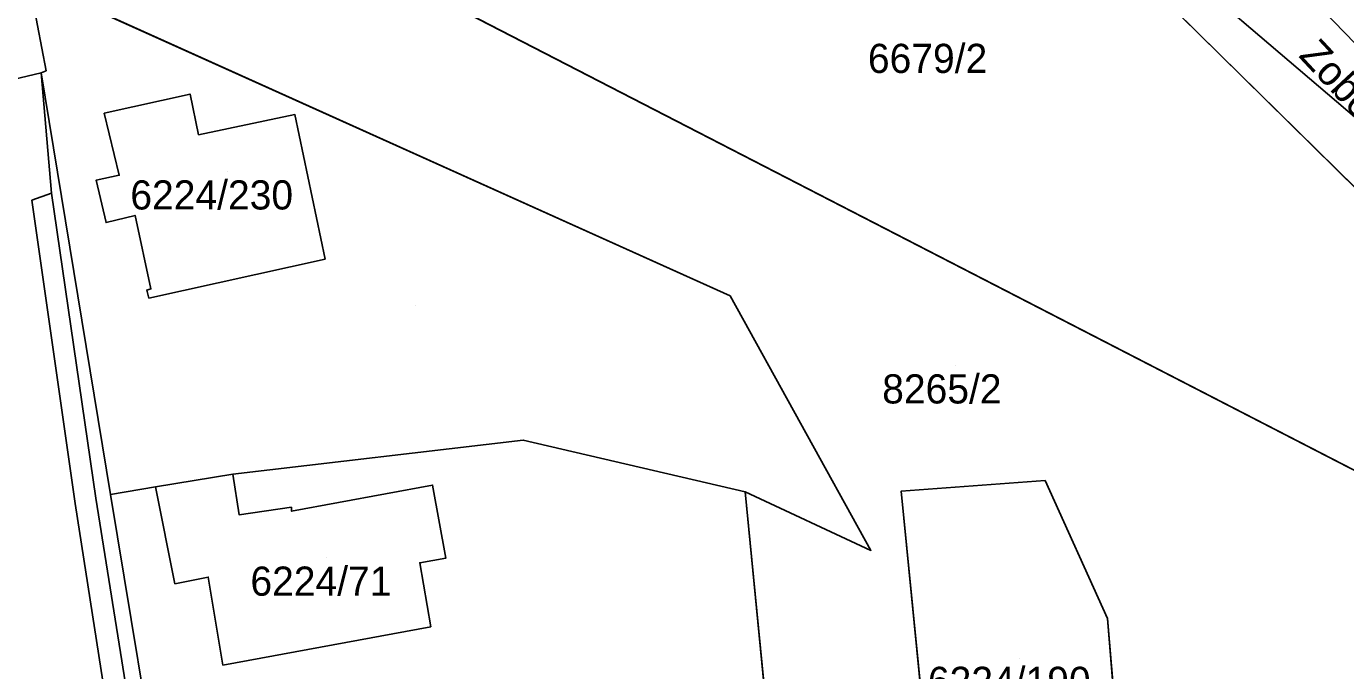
# Model space of a CAD drawing. Extents: x -266199 to -261993, y -1239047 to -1235108.
# Drawn here: x -263852.9 to -263762.5, y -1235880.6 to -1235836.4 of the extents above; entities that cross this region are included whole.
import ezdxf

# ---------------------------------------------------------------- set-up
doc = ezdxf.new("R2010")
doc.units = 0
for name, color, linetype in [('body_kn', 7, 'Continuous'), ('kladpar_druhypozemkov', 7, 'Continuous'), ('kladpar_hranice', 7, 'Continuous'), ('kladpar_parcelnecisla', 7, 'Continuous'), ('kladpar_plochy', 7, 'Continuous'), ('popisy', 7, 'Continuous'), ('zappar_hrandruhpozemk', 7, 'Continuous'), ('zuob_linie', 7, 'Continuous'), ('zuob_plochy', 7, 'Continuous')]:
    doc.layers.add(name, color=color, linetype=linetype)

msp = doc.modelspace()

# ---------------------------------------------------------------- linework, layer by layer
at = {"layer": 'body_kn'}
for p, q in [((-263851.59, -1235839.47), (-263851.59, -1235839.47)), ((-263851.92, -1235839.62), (-263851.92, -1235839.62)), ((-263851.92, -1235839.62), (-263851.92, -1235839.62)), ((-263841.72, -1235841.07), (-263841.72, -1235841.07)), ((-263847.6, -1235842.38), (-263847.6, -1235842.38)), ((-263847.6, -1235842.38), (-263847.6, -1235842.38)), ((-263834.54, -1235842.47), (-263834.54, -1235842.47)), ((-263841.14, -1235843.86), (-263841.14, -1235843.86)), ((-263846.58, -1235846.63), (-263846.58, -1235846.63)), ((-263848.16, -1235846.98), (-263848.16, -1235846.98)), ((-263852.57, -1235848.34), (-263852.57, -1235848.34)), ((-263851.22, -1235847.85), (-263851.22, -1235847.85)), ((-263845.49, -1235849.39), (-263845.49, -1235849.39)), ((-263847.48, -1235849.88), (-263847.48, -1235849.88)), ((-263832.46, -1235852.38), (-263832.46, -1235852.38)), ((-263844.69, -1235854.51), (-263844.69, -1235854.51)), ((-263844.4, -1235854.43), (-263844.4, -1235854.43)), ((-263804.71, -1235854.89), (-263804.71, -1235854.89)), ((-263844.55, -1235855.05), (-263844.55, -1235855.05)), ((-263818.89, -1235864.79), (-263818.89, -1235864.79)), ((-263838.8, -1235867.12), (-263838.8, -1235867.12)), ((-263838.8, -1235867.12), (-263838.8, -1235867.12)), ((-263783.13, -1235867.56), (-263783.13, -1235867.56)), ((-263847.17, -1235868.53), (-263847.17, -1235868.53)), ((-263844.09, -1235867.99), (-263844.09, -1235867.99)), ((-263825.1, -1235867.87), (-263825.1, -1235867.87)), ((-263803.68, -1235868.33), (-263803.68, -1235868.33)), ((-263803.68, -1235868.33), (-263803.68, -1235868.33)), ((-263792.98, -1235868.29), (-263792.98, -1235868.29)), ((-263792.98, -1235868.29), (-263792.98, -1235868.29)), ((-263849.6, -1235869.13), (-263849.6, -1235869.13)), ((-263848.17, -1235868.77), (-263848.17, -1235868.77)), ((-263834.78, -1235869.39), (-263834.78, -1235869.39)), ((-263838.36, -1235869.91), (-263838.36, -1235869.91)), ((-263834.76, -1235869.67), (-263834.76, -1235869.67)), ((-263824.19, -1235872.88), (-263824.19, -1235872.88)), ((-263795.06, -1235872.35), (-263795.06, -1235872.35)), ((-263825.98, -1235873.2), (-263825.98, -1235873.2)), ((-263842.76, -1235874.64), (-263842.76, -1235874.64)), ((-263840.48, -1235874.18), (-263840.48, -1235874.18)), ((-263778.86, -1235877.02), (-263778.86, -1235877.02)), ((-263825.23, -1235877.59), (-263825.23, -1235877.59)), ((-263839.47, -1235880.23), (-263839.47, -1235880.23))]:
    msp.add_line(p, q, dxfattribs=at)
at = {"layer": 'kladpar_druhypozemkov'}
for p, q in [((-263791.34, -1235837.47), (-263791.34, -1235837.47)), ((-263839.13, -1235846.38), (-263839.13, -1235846.38)), ((-263826.27, -1235855.59), (-263826.27, -1235855.59)), ((-263789.29, -1235859.68), (-263789.29, -1235859.68)), ((-263832.36, -1235872.86), (-263832.36, -1235872.86)), ((-263784.89, -1235879.73), (-263784.89, -1235879.73))]:
    msp.add_line(p, q, dxfattribs=at)
at = {"layer": 'kladpar_hranice'}
msp.add_line((-263790.19, -1235819.57), (-263745.77, -1235863.37), dxfattribs=at)
for points in [[(-263852.77, -1235833.23), (-263851.59, -1235839.47), (-263851.92, -1235839.62), (-263862.87, -1235842.21), (-263869.05, -1235843.63), (-263875.77, -1235843.21), (-263876.54, -1235843.16), (-263887.37, -1235841.2), (-263889.51, -1235841.55), (-263889.97, -1235824.08), (-263890.32, -1235807.25)], [(-263790.19, -1235819.57), (-263788.6, -1235816.64), (-263787.01, -1235817.36), (-263775.38, -1235816.08), (-263773.44, -1235825.65), (-263750.35, -1235849.51), (-263746.44, -1235854.19), (-263744.9, -1235861.03), (-263743.98, -1235865.13)], [(-263743.98, -1235865.13), (-263745.77, -1235863.37), (-263790.19, -1235819.57)], [(-263852.77, -1235833.23), (-263847.9, -1235831.61), (-263850.39, -1235825.64), (-263852.91, -1235819.95), (-263760.04, -1235867.84), (-263755.07, -1235870.59), (-263753.46, -1235878.11), (-263751.22, -1235888.59), (-263750.45, -1235888.68), (-263742.9, -1235890.11), (-263743.29, -1235891.8), (-263745, -1235896.53), (-263745.24, -1235898.04), (-263747.36, -1235898.32), (-263749.24, -1235899.52), (-263750.3, -1235903.8), (-263750.26, -1235906.01), (-263749.84, -1235908.26), (-263742.33, -1235932.99), (-263735.92, -1235952.6), (-263730.02, -1235970.1)], [(-263745.77, -1235863.37), (-263755.07, -1235870.59), (-263760.04, -1235867.84), (-263852.91, -1235819.95)], [(-263752.76, -1235826.07), (-263746.44, -1235854.19), (-263750.35, -1235849.51), (-263773.44, -1235825.65)], [(-263852.77, -1235833.23), (-263804.71, -1235854.89), (-263795.06, -1235872.35), (-263803.68, -1235868.33)], [(-263803.68, -1235868.33), (-263818.89, -1235864.79), (-263838.8, -1235867.12), (-263844.09, -1235867.99), (-263847.17, -1235868.53), (-263851.92, -1235839.62), (-263851.59, -1235839.47), (-263852.77, -1235833.23)], [(-263803.68, -1235868.33), (-263795.06, -1235872.35), (-263804.71, -1235854.89), (-263852.77, -1235833.23)], [(-263862.87, -1235842.21), (-263851.92, -1235839.62), (-263847.17, -1235868.53), (-263843.4, -1235891.32), (-263839.97, -1235913.92), (-263836.32, -1235935.66), (-263831.56, -1235966.75)], [(-263803.68, -1235868.33), (-263801.72, -1235888.37), (-263843.4, -1235891.32), (-263847.17, -1235868.53), (-263844.09, -1235867.99), (-263838.8, -1235867.12), (-263818.89, -1235864.79), (-263803.68, -1235868.33)], [(-263791.01, -1235888.29), (-263792.98, -1235868.29), (-263783.13, -1235867.56), (-263778.86, -1235877.02), (-263778.03, -1235886.75), (-263784.73, -1235896.53), (-263791.01, -1235888.29)], [(-263792.98, -1235868.29), (-263791.01, -1235888.29), (-263784.73, -1235896.53), (-263778.03, -1235886.75), (-263778.86, -1235877.02), (-263783.13, -1235867.56), (-263792.98, -1235868.29)], [(-263765.34, -1235966.31), (-263767.35, -1235955.29), (-263768.96, -1235955.6), (-263776.64, -1235936.12), (-263778.32, -1235931.56), (-263777.38, -1235929.72), (-263781.37, -1235927.17), (-263787.97, -1235921.62), (-263789.73, -1235919.93), (-263792.64, -1235910.53), (-263795.23, -1235910.93), (-263800.52, -1235892.55), (-263801.72, -1235888.37), (-263803.68, -1235868.33)]]:
    msp.add_lwpolyline(points, dxfattribs=at)
at = {"layer": 'kladpar_plochy'}
for p, q in [((-263852.91, -1235819.95), (-263760.04, -1235867.84)), ((-263804.71, -1235854.89), (-263852.77, -1235833.23)), ((-263795.06, -1235872.35), (-263804.71, -1235854.89)), ((-263783.13, -1235867.56), (-263792.98, -1235868.29)), ((-263778.86, -1235877.02), (-263783.13, -1235867.56)), ((-263801.72, -1235888.37), (-263803.68, -1235868.33)), ((-263803.68, -1235868.33), (-263795.06, -1235872.35)), ((-263792.98, -1235868.29), (-263791.01, -1235888.29)), ((-263778.03, -1235886.75), (-263778.86, -1235877.02))]:
    msp.add_line(p, q, dxfattribs=at)
for points in [[(-263890.32, -1235807.25), (-263890.36, -1235799.89), (-263890.37, -1235797.68), (-263869.55, -1235819.97), (-263859.45, -1235816.34), (-263852.77, -1235833.23), (-263851.59, -1235839.47), (-263851.92, -1235839.62), (-263862.87, -1235842.21), (-263869.05, -1235843.63), (-263875.77, -1235843.21), (-263876.54, -1235843.16), (-263887.37, -1235841.2), (-263889.51, -1235841.55), (-263889.97, -1235824.08)], [(-263852.91, -1235819.95), (-263813.05, -1235804.46), (-263808.94, -1235808.94), (-263799.41, -1235816.29), (-263792.65, -1235818.94), (-263790.19, -1235819.57), (-263745.77, -1235863.37), (-263755.07, -1235870.59), (-263760.04, -1235867.84)], [(-263790.19, -1235819.57), (-263788.6, -1235816.64), (-263787.01, -1235817.36), (-263775.38, -1235816.08), (-263773.44, -1235825.65), (-263750.35, -1235849.51), (-263746.44, -1235854.19), (-263744.9, -1235861.03), (-263743.98, -1235865.13), (-263745.77, -1235863.37)], [(-263852.77, -1235833.23), (-263804.71, -1235854.89), (-263795.06, -1235872.35), (-263803.68, -1235868.33), (-263818.89, -1235864.79), (-263838.8, -1235867.12), (-263844.09, -1235867.99), (-263847.17, -1235868.53), (-263851.92, -1235839.62), (-263851.59, -1235839.47)], [(-263803.68, -1235868.33), (-263801.72, -1235888.37), (-263843.4, -1235891.32), (-263847.17, -1235868.53), (-263844.09, -1235867.99), (-263838.8, -1235867.12), (-263818.89, -1235864.79)], [(-263791.01, -1235888.29), (-263792.98, -1235868.29), (-263783.13, -1235867.56), (-263778.86, -1235877.02), (-263778.03, -1235886.75), (-263784.73, -1235896.53)]]:
    msp.add_lwpolyline(points, close=True, dxfattribs=at)
for points in [[(-263752.76, -1235826.07), (-263746.44, -1235854.19), (-263750.35, -1235849.51), (-263773.44, -1235825.65)], [(-263862.87, -1235842.21), (-263851.92, -1235839.62), (-263847.17, -1235868.53), (-263843.4, -1235891.32), (-263839.97, -1235913.92), (-263836.32, -1235935.66), (-263831.56, -1235966.75)]]:
    msp.add_lwpolyline(points, dxfattribs=at)
at = {"layer": 'zappar_hrandruhpozemk'}
for p, q in [((-263851.92, -1235839.62), (-263851.22, -1235847.85)), ((-263852.57, -1235848.34), (-263849.6, -1235869.13)), ((-263844.55, -1235855.05), (-263832.46, -1235852.38)), ((-263844.55, -1235891.6), (-263848.17, -1235868.77)), ((-263825.23, -1235877.59), (-263839.47, -1235880.23))]:
    msp.add_line(p, q, dxfattribs=at)
for points in [[(-263790.19, -1235819.57), (-263777.69, -1235829.16), (-263761.75, -1235842.76)], [(-263832.46, -1235852.38), (-263834.54, -1235842.47), (-263841.14, -1235843.86), (-263841.72, -1235841.07), (-263847.6, -1235842.38)], [(-263847.6, -1235842.38), (-263846.58, -1235846.63), (-263848.16, -1235846.98), (-263847.48, -1235849.88), (-263845.49, -1235849.39), (-263844.4, -1235854.43), (-263844.69, -1235854.51), (-263844.55, -1235855.05)], [(-263848.17, -1235868.77), (-263851.22, -1235847.85), (-263852.57, -1235848.34)], [(-263838.8, -1235867.12), (-263838.36, -1235869.91), (-263834.78, -1235869.39), (-263834.76, -1235869.67), (-263825.1, -1235867.87), (-263824.19, -1235872.88), (-263825.98, -1235873.2), (-263825.23, -1235877.59)], [(-263839.47, -1235880.23), (-263840.48, -1235874.18), (-263842.76, -1235874.64), (-263844.09, -1235867.99)], [(-263849.6, -1235869.13), (-263846.09, -1235891.73), (-263842.63, -1235913.99)]]:
    msp.add_lwpolyline(points, dxfattribs=at)
at = {"layer": 'zuob_linie'}
msp.add_lwpolyline([(-263933.13, -1235712.77), (-263894.65, -1235777.08), (-263863.57, -1235809.58), (-263861.99, -1235809.36), (-263856.22, -1235812.47), (-263852.91, -1235819.95), (-263760.04, -1235867.84), (-263755.07, -1235870.59), (-263741, -1235878.38), (-263723.84, -1235887.88), (-263721.78, -1235889.02), (-263719.13, -1235890.49), (-263717.14, -1235891.59), (-263715.75, -1235892.23), (-263680.14, -1235908.53), (-263582.85, -1235873.67)], dxfattribs=at)
at = {"layer": 'zuob_plochy'}
msp.add_lwpolyline([(-263933.13, -1235712.77), (-263894.65, -1235777.08), (-263863.57, -1235809.58), (-263861.99, -1235809.36), (-263856.22, -1235812.47), (-263852.91, -1235819.95), (-263760.04, -1235867.84), (-263755.07, -1235870.59), (-263741, -1235878.38), (-263723.84, -1235887.88), (-263721.78, -1235889.02), (-263719.13, -1235890.49), (-263717.14, -1235891.59), (-263715.75, -1235892.23), (-263680.14, -1235908.53), (-263582.85, -1235873.67)], dxfattribs=at)

# ---------------------------------------------------------------- texts
at = {"layer": 'kladpar_parcelnecisla'}
for s, p in [('6679/2', (-263795.269, -1235839.62)), ('6224/230', (-263845.816, -1235848.98)), ('8265/2', (-263794.29, -1235862.28)), ('6224/71', (-263837.587, -1235875.46)), ('6224/190', (-263791.157, -1235882.33))]:
    msp.add_text(s, height=2, dxfattribs=at).set_placement(p)
at = {"layer": 'popisy'}
msp.add_text('Zoborská', height=2, rotation=313, dxfattribs=at).set_placement((-263765.804, -1235838.472))

doc.saveas('drawing.dxf')
